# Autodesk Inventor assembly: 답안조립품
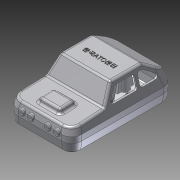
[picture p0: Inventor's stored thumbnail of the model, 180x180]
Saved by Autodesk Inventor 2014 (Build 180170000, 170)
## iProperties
Created: 2015-05
Part Number: 답안조립품
Document SubType Name: Assembly
Designer: Administrator
Author: Administrator
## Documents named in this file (7)
- C:\Documents and Settings\Administrator\바탕 화면\2015.05.23\답안조립품.iam
- C:\Documents and Settings\Administrator\바탕 화면\2015.05.23\본체.ipt
- C:\Documents and Settings\Administrator\바탕 화면\2015.05.23\커버.ipt
- C:\Documents and Settings\Administrator\바탕 화면\2015.05.23\바퀴.ipt
- C:\Documents and Settings\Administrator\바탕 화면\2015.05.23\바퀴고정부.ipt
- C:\Documents and Settings\Administrator\바탕 화면\2015.05.23\M2x4.ipt
- C:\Documents and Settings\Administrator\바탕 화면\2015.05.23\M4x10.ipt
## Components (20 placed, 2 different names)
1. M2x4:1
2. M2x4:2
3. M2x4:3
4. M2x4:4
5. M2x4:5
6. M2x4:6
7. M2x4:7
8. M2x4:8
9. M2x4:9
10. M2x4:10
11. M2x4:11
12. M2x4:12
13. M2x4:13
14. M2x4:14
15. M2x4:15
16. M2x4:16
17. M4x10:1
18. M4x10:2
19. M4x10:3
20. M4x10:4
